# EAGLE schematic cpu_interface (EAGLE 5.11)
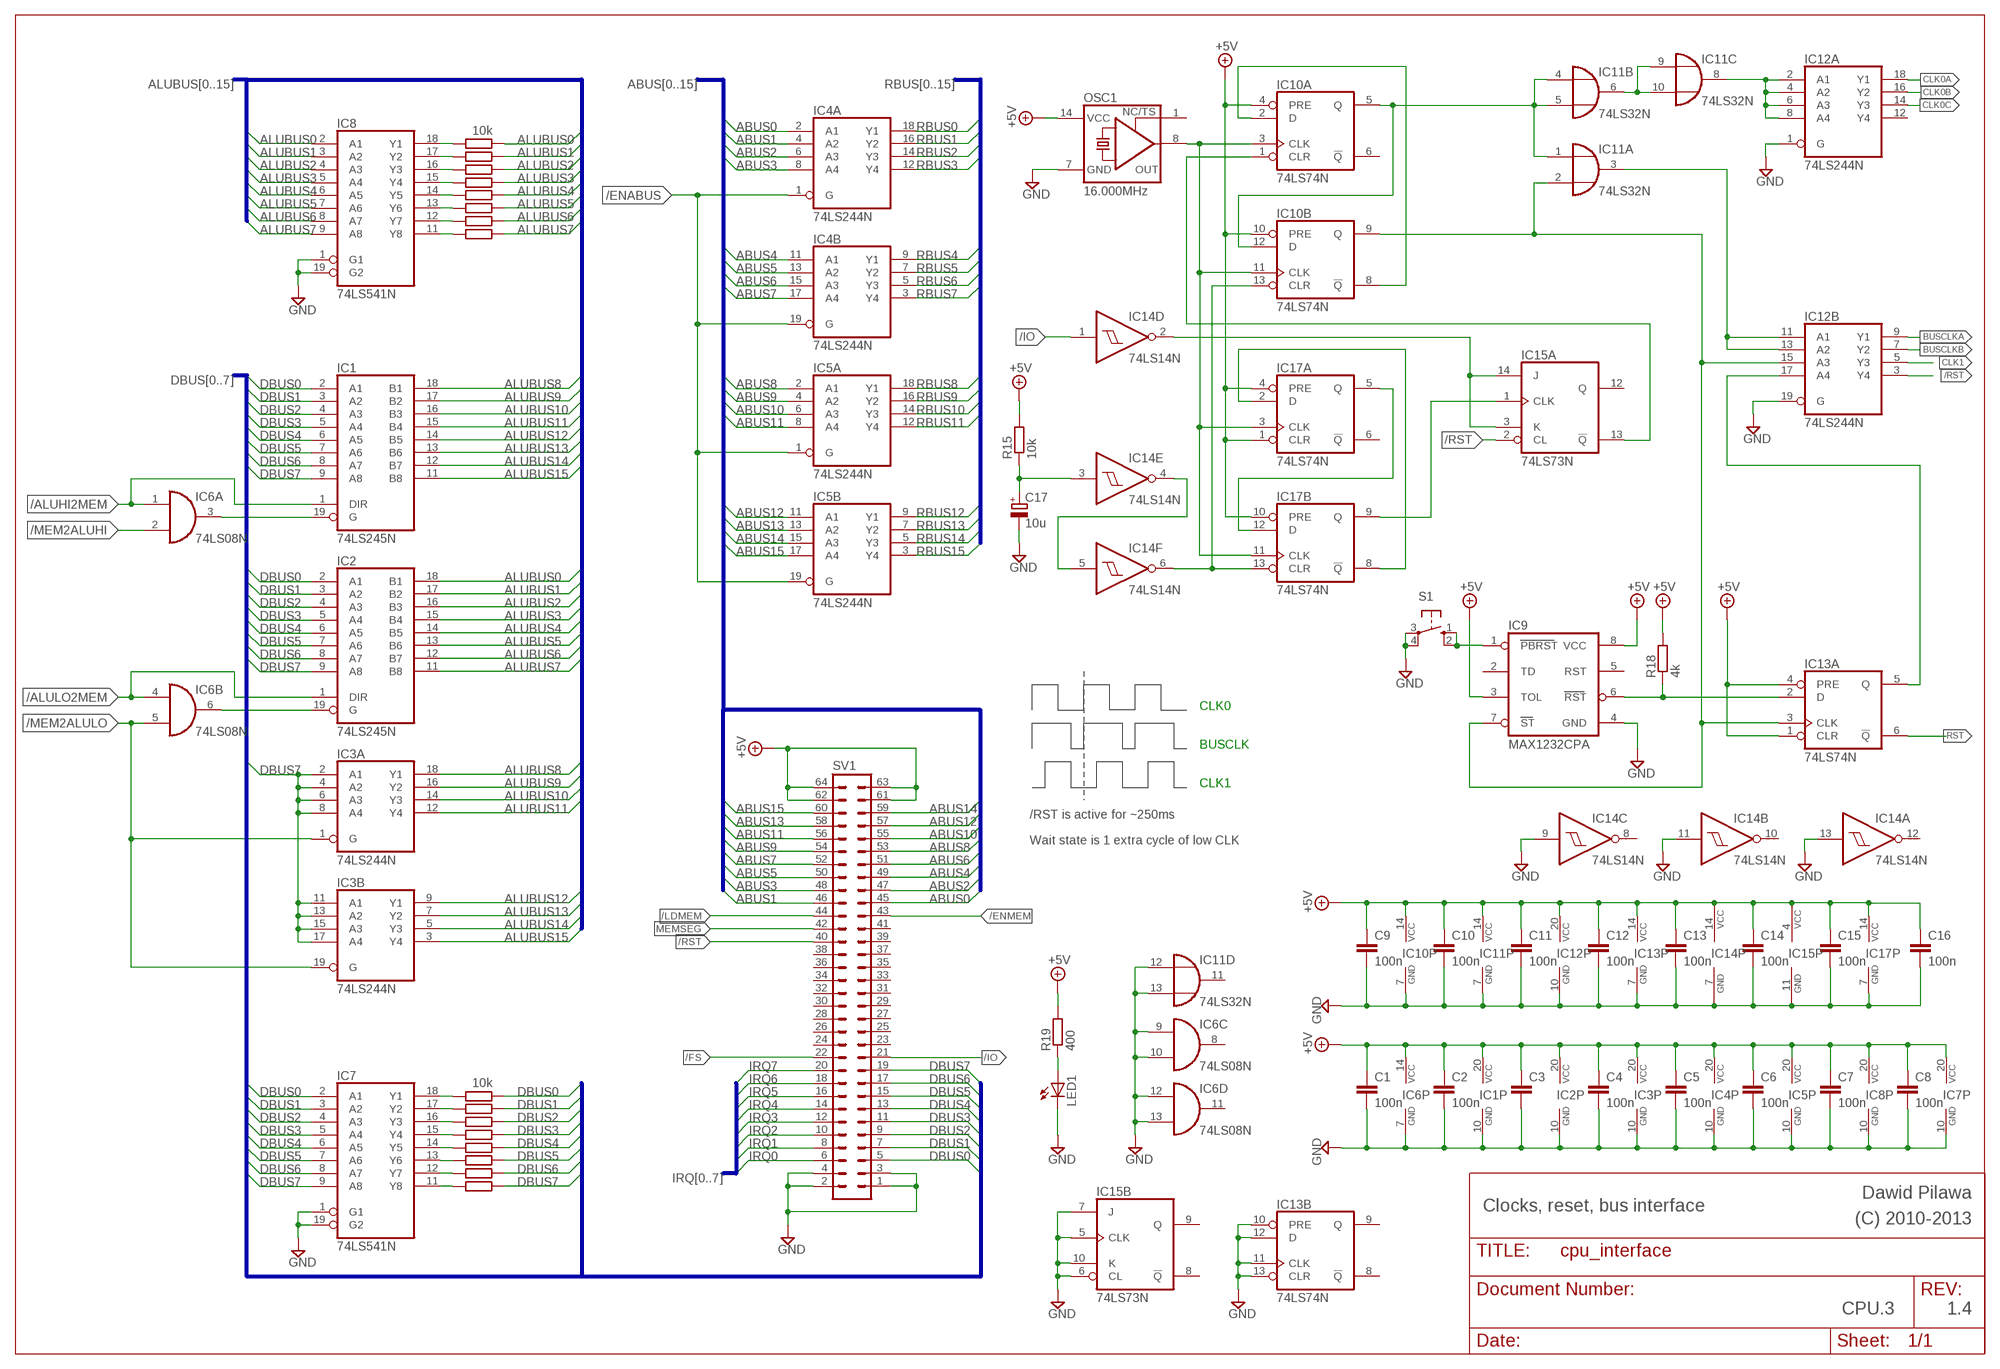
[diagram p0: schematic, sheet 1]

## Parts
C1  100n  C-EU050-024X044  [C050-024X044]
C2  100n  C-EU050-024X044  [C050-024X044]
C3  C-EU050-024X044  [C050-024X044]
C4  100n  C-EU050-024X044  [C050-024X044]
C5  100n  C-EU050-024X044  [C050-024X044]
C6  100n  C-EU050-024X044  [C050-024X044]
C7  100n  C-EU050-024X044  [C050-024X044]
C8  100n  C-EU050-024X044  [C050-024X044]
C9  100n  C-EU050-024X044  [C050-024X044]
C10  100n  C-EU050-024X044  [C050-024X044]
C11  100n  C-EU050-024X044  [C050-024X044]
C12  100n  C-EU050-024X044  [C050-024X044]
C13  100n  C-EU050-024X044  [C050-024X044]
C14  100n  C-EU050-024X044  [C050-024X044]
C15  100n  C-EU050-024X044  [C050-024X044]
C16  100n  C-EU050-024X044  [C050-024X044]
C17  10u  CPOL-EUE2.5-5  [E2,5-5]
IC1  74LS245N  [DIL20]
IC2  74LS245N  [DIL20]
IC3  74LS244N  [DIL20]
IC4  74LS244N  [DIL20]
IC5  74LS244N  [DIL20]
IC6  74LS08N  [DIL14]
IC7  74LS541N  [DIL20]
IC8  74LS541N  [DIL20]
IC9  MAX1232CPA  [DIL08]
IC10  74LS74N  [DIL14]
IC11  74LS32N  [DIL14]
IC12  74LS244N  [DIL20]
IC13  74LS74N  [DIL14]
IC14  74LS14N  [DIL14]
IC15  74LS73N  [DIL14]
IC17  74LS74N  [DIL14]
LED1  LED5MM  [LED5MM]
OSC1  16.000MHz  XO-14  [DIL14S]
R1  10k  R-EU_0207/7  [0207/7]
R2  R-EU_0207/7  [0207/7]
R3  R-EU_0207/7  [0207/7]
R4  R-EU_0207/7  [0207/7]
R5  R-EU_0207/7  [0207/7]
R6  R-EU_0207/7  [0207/7]
R7  10k  R-EU_0207/7  [0207/7]
R8  10k  R-EU_0207/7  [0207/7]
R9  10k  R-EU_0207/7  [0207/7]
R10  10k  R-EU_0207/7  [0207/7]
R11  10k  R-EU_0207/7  [0207/7]
R12  10k  R-EU_0207/7  [0207/7]
R13  10k  R-EU_0207/7  [0207/7]
R14  10k  R-EU_0207/7  [0207/7]
R15  10k  R-EU_0204/7  [0204/7]
R16  10k  R-EU_0207/7  [0207/7]
R17  10k  R-EU_0207/7  [0207/7]
R18  4k  R-EU_0204/5  [0204/5]
R19  400  R-EU_0204/5  [0204/5]
S1  10-XX  [B3F-10XX]
SV1  ML64L  [ML64L]

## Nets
+5V: C1.1 C2.1 C3.1 C4.1 C5.1 C6.1 C7.1 C8.1 C9.1 C10.1 C11.1 C12.1 C13.1 C14.1 C15.1 C16.1 IC1.20(VCC) IC2.20(VCC) IC3.20(P:VCC) IC4.20(P:VCC) IC5.20(P:VCC) IC6.14(P:VCC) IC7.20(VCC) IC8.20(VCC) IC9.3(TOL) IC9.8(VCC) IC10.4(A:PRE) IC10.10(B:PRE) IC10.14(P:VCC) IC11.14(P:VCC) IC12.20(P:VCC) IC13.1(A:CLR) IC13.4(A:PRE) IC13.14(P:VCC) IC14.14(P:VCC) IC15.4(P:VCC) IC17.1(A:CLR) IC17.4(A:PRE) IC17.10(B:PRE) IC17.14(P:VCC) OSC1.14(VCC) R15.2 R18.2 R19.2 SV1.61 SV1.62 SV1.63 SV1.64
/ALUHI2MEM: IC1.1(DIR) IC6.1(A:I0)
/ALULO2MEM: IC2.1(DIR) IC6.4(B:I0)
/ENABUS: IC4.1(A:G) IC4.19(B:G) IC5.1(A:G) IC5.19(B:G)
/ENMEM: SV1.43
/FS: SV1.22
/IO: IC14.1(D:I) SV1.21
/LDMEM: SV1.44
/MEM2ALUHI: IC6.2(A:I1)
/MEM2ALULO: IC3.1(A:G) IC3.19(B:G) IC6.5(B:I1)
/RST: IC12.3(B:Y4) IC15.2(A:CL) SV1.40
ABUS0: IC4.2(A:A1) SV1.45
ABUS1: IC4.4(A:A2) SV1.46
ABUS2: IC4.6(A:A3) SV1.47
ABUS3: IC4.8(A:A4) SV1.48
ABUS4: IC4.11(B:A1) SV1.49
ABUS5: IC4.13(B:A2) SV1.50
ABUS6: IC4.15(B:A3) SV1.51
ABUS7: IC4.17(B:A4) SV1.52
ABUS8: IC5.2(A:A1) SV1.53
ABUS9: IC5.4(A:A2) SV1.54
ABUS10: IC5.6(A:A3) SV1.55
ABUS11: IC5.8(A:A4) SV1.56
ABUS12: IC5.11(B:A1) SV1.57
ABUS13: IC5.13(B:A2) SV1.58
ABUS14: IC5.15(B:A3) SV1.59
ABUS15: IC5.17(B:A4) SV1.60
ALUBUS0: IC2.18(B1) IC8.2(A1) R1.2
ALUBUS1: IC2.17(B2) IC8.3(A2) R2.2
ALUBUS2: IC2.16(B3) IC8.4(A3) R3.2
ALUBUS3: IC2.15(B4) IC8.5(A4) R4.2
ALUBUS4: IC2.14(B5) IC8.6(A5) R5.2
ALUBUS5: IC2.13(B6) IC8.7(A6) R6.2
ALUBUS6: IC2.12(B7) IC8.8(A7) R7.2
ALUBUS7: IC2.11(B8) IC8.9(A8) R8.2
ALUBUS8: IC1.18(B1) IC3.18(A:Y1)
ALUBUS9: IC1.17(B2) IC3.16(A:Y2)
ALUBUS10: IC1.16(B3) IC3.14(A:Y3)
ALUBUS11: IC1.15(B4) IC3.12(A:Y4)
ALUBUS12: IC1.14(B5) IC3.9(B:Y1)
ALUBUS13: IC1.13(B6) IC3.7(B:Y2)
ALUBUS14: IC1.12(B7) IC3.5(B:Y3)
ALUBUS15: IC1.11(B8) IC3.3(B:Y4)
BUSCLK: IC11.3(A:O) IC12.11(B:A1) IC12.13(B:A2)
BUSCLKA: IC12.9(B:Y1)
BUSCLKB: IC12.7(B:Y2)
CLK0: IC10.5(A:Q) IC10.12(B:D) IC11.1(A:I0) IC11.4(B:I0) IC11.5(B:I1)
CLK0A: IC12.18(A:Y1)
CLK0B: IC12.16(A:Y2)
CLK0C: IC12.14(A:Y3)
CLK1: IC12.5(B:Y3)
DBUS0: IC1.2(A1) IC2.2(A1) IC7.2(A1) R9.2 SV1.5
DBUS1: IC1.3(A2) IC2.3(A2) IC7.3(A2) R10.2 SV1.7
DBUS2: IC1.4(A3) IC2.4(A3) IC7.4(A3) R11.2 SV1.9
DBUS3: IC1.5(A4) IC2.5(A4) IC7.5(A4) R12.2 SV1.11
DBUS4: IC1.6(A5) IC2.6(A5) IC7.6(A5) R13.2 SV1.13
DBUS5: IC1.7(A6) IC2.7(A6) IC7.7(A6) R14.2 SV1.15
DBUS6: IC1.8(A7) IC2.8(A7) IC7.8(A7) R16.2 SV1.17
DBUS7: IC1.9(A8) IC2.9(A8) IC3.2(A:A1) IC3.4(A:A2) IC3.6(A:A3) IC3.8(A:A4) IC3.11(B:A1) IC3.13(B:A2) IC3.15(B:A3) IC3.17(B:A4) IC7.9(A8) R17.2 SV1.19
GND: C1.2 C2.2 C3.2 C4.2 C5.2 C6.2 C7.2 C8.2 C9.2 C10.2 C11.2 C12.2 C13.2 C14.2 C15.2 C16.2 C17.- IC1.10(GND) IC2.10(GND) IC3.10(P:GND) IC4.10(P:GND) IC5.10(P:GND) IC6.7(P:GND) IC6.9(C:I0) IC6.10(C:I1) IC6.12(D:I0) IC6.13(D:I1) IC7.1(G1) IC7.10(GND) IC7.19(G2) IC8.1(G1) IC8.10(GND) IC8.19(G2) IC9.4(GND) IC10.7(P:GND) IC11.7(P:GND) IC11.12(D:I0) IC11.13(D:I1) IC12.1(A:G) IC12.10(P:GND) IC12.19(B:G) IC13.7(P:GND) IC13.10(B:PRE) IC13.11(B:CLK) IC13.12(B:D) IC13.13(B:CLR) IC14.7(P:GND) IC14.9(C:I) IC14.11(B:I) IC14.13(A:I) IC15.5(B:CLK) IC15.6(B:CL) IC15.7(B:J) IC15.10(B:K) IC15.11(P:GND) IC17.7(P:GND) LED1.K(C) OSC1.7(GND) S1.3(P) S1.4(P1) SV1.1 SV1.2 SV1.3 SV1.4
IRQ0: SV1.6
IRQ1: SV1.8
IRQ2: SV1.10
IRQ3: SV1.12
IRQ4: SV1.14
IRQ5: SV1.16
IRQ6: SV1.18
IRQ7: SV1.20
MEMSEG: SV1.42
N$1: IC1.19(G) IC6.3(A:O)
N$2: IC2.19(G) IC6.6(B:O)
N$3: IC8.18(Y1) R1.1
N$4: IC8.17(Y2) R2.1
N$5: IC8.16(Y3) R3.1
N$6: IC8.15(Y4) R4.1
N$7: IC8.14(Y5) R5.1
N$8: IC8.13(Y6) R6.1
N$9: IC8.12(Y7) R7.1
N$10: IC8.11(Y8) R8.1
N$11: IC7.18(Y1) R9.1
N$12: IC7.17(Y2) R10.1
N$13: IC7.16(Y3) R11.1
N$14: IC7.15(Y4) R12.1
N$15: IC7.14(Y5) R13.1
N$16: IC7.12(Y7) R16.1
N$17: IC7.11(Y8) R17.1
N$18: IC7.13(Y6) R14.1
N$19: IC9.1(PBRST) S1.1(S) S1.2(S1)
N$20: IC10.3(A:CLK) IC10.11(B:CLK) IC17.3(A:CLK) IC17.11(B:CLK) OSC1.8(OUT)
N$21: LED1.A R19.1
N$22: IC10.2(A:D) IC10.8(B:!Q)
N$23: IC12.17(B:A4) IC13.5(A:Q)
N$24: IC9.6(RST) IC13.2(A:D) R18.1
N$25: IC17.2(A:D) IC17.8(B:!Q)
N$26: IC11.8(C:O) IC12.2(A:A1) IC12.4(A:A2) IC12.6(A:A3) IC12.8(A:A4)
N$27: IC10.1(A:CLR) IC15.13(A:!Q)
N$28: C17.+ IC14.3(E:I) R15.1
N$29: IC11.6(B:O) IC11.9(C:I0) IC11.10(C:I1)
N$30: IC9.7(ST) IC10.9(B:Q) IC11.2(A:I1) IC12.15(B:A3) IC13.3(A:CLK)
N$31: IC17.5(A:Q) IC17.12(B:D)
N$32: IC15.1(A:CLK) IC17.9(B:Q)
N$33: IC14.2(D:O) IC15.3(A:K) IC15.14(A:J)
N$34: IC14.4(E:O) IC14.5(F:I)
N$35: IC10.13(B:CLR) IC14.6(F:O) IC17.13(B:CLR)
RBUS0: IC4.18(A:Y1)
RBUS1: IC4.16(A:Y2)
RBUS2: IC4.14(A:Y3)
RBUS3: IC4.12(A:Y4)
RBUS4: IC4.9(B:Y1)
RBUS5: IC4.7(B:Y2)
RBUS6: IC4.5(B:Y3)
RBUS7: IC4.3(B:Y4)
RBUS8: IC5.18(A:Y1)
RBUS9: IC5.16(A:Y2)
RBUS10: IC5.14(A:Y3)
RBUS11: IC5.12(A:Y4)
RBUS12: IC5.9(B:Y1)
RBUS13: IC5.7(B:Y2)
RBUS14: IC5.5(B:Y3)
RBUS15: IC5.3(B:Y4)
RST: IC13.6(A:!Q)
Unconnected: IC6.8(C:O) IC6.11(D:O) IC9.2(TD) IC9.5(RST) IC10.6(A:!Q) IC11.11(D:O) IC12.12(A:Y4) IC13.8(B:!Q) IC13.9(B:Q) IC14.8(C:O) IC14.10(B:O) IC14.12(A:O) IC15.8(B:!Q) IC15.9(B:Q) IC15.12(A:Q) IC17.6(A:!Q) OSC1.1(TS) SV1.23 SV1.24 SV1.25 SV1.26 SV1.27 SV1.28 SV1.29 SV1.30 SV1.31 SV1.32 SV1.33 SV1.34 SV1.35 SV1.36 SV1.37 SV1.38 SV1.39 SV1.41

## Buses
DBUS[0..7]
ALUBUS[0..15]
RBUS[0..15]
IRQ[0..7]
ABUS[0..15]

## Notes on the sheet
- CLK0
- BUSCLK
- CLK1
- /RST is active for ~250ms
- Wait state is 1 extra cycle of low CLK
- Dawid Pilawa
- Clocks, reset, bus interface | (C) 2010-2013
- CPU.3 | 1.4

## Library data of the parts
C1-C16 = rcl:C-EU: CAPACITOR, European symbol
C17 = rcl:CPOL-EU: POLARIZED CAPACITOR, European symbol
IC1 IC2 = 74xx-eu:74*245: Octal BUS TRANSCEIVER, 3-state
IC3-IC5 IC12 = 74xx-eu:74*244: Octal BUFFER and LINE DRIVER, 3-state
IC6 = 74xx-eu:74*08: Quad 2-input AND gate
IC7 IC8 = 74xx-eu:74*541: Octal BUFFER and LINE DRIVER, 3-state
IC9 = maxim:MAX1232CPA: MONITOR DEVICE
IC10 IC13 IC17 = 74xx-eu:74*74: Dual D type positive edge triggered FLIP FLOP, preset and clear
IC11 = 74xx-eu:74*32: Quad 2-input OR gate
IC14 = 74xx-us:74*14: Hex schmitt trigger INVERTER
IC15 = 74xx-us:74*73: Dual J-K FLIP FLOP, clear
LED1 = led:LED: LED
OSC1 = crystal:XO-: CRYSTAL
R1-R19 = rcl:R-EU_: RESISTOR, European symbol
S1 = switch-omron:10-XX: OMRON SWITCH
SV1 = con-harting-ml:ML64: HARTING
